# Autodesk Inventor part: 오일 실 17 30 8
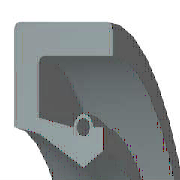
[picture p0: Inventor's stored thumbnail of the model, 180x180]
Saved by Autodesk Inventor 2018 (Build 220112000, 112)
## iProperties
Created: 2012-02
Part Number: 오일 실 17 30 8
Material: 고무
Description: 오일-실
Document SubType Name: Modeling
Standard: KS B 2804
Designer: mduedu
Standards Organization: KS
Language: ko-KR
Size Designation: S - 17 30 8
Categories: <MemberInstance><Categories><Category DisplayName="샤프트 부품" InternalName="7f7aeb1f-a693-4053-b835-cee3144e0d98" Mnemonic="SHFT"><Category DisplayName="실링" Intern
Density: 0.93 g/cm^3
Appearance: 고무 - 검은색 - 버전 1.1
IsCustomPart: 1
Author: mduedu
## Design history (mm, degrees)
revolve "본체" stored, may be unused: angle "d17" = 90 deg
revolve "스프링1" stored, may be unused: angle "d18" = 90 deg
body "Solid1"
sketch "스케치1"
  geometry: L1 (0, 15)-(8, 15); L2 (8, 15)-(8, 13.75); L3 (8, 13.75)-(1.75, 13.75); L4 (0, 15)-(0, 10.6); L5 (0, 10.6)-(1.75, 10.25); L6 (1.75, 10.25)-(4.9, 8.5); L7 (4.9, 8.5)-(0, 8.5); L8 (6.3, 9.375)-(6.3, 10.6); L9 (0, 0)-(9.586, 0) reference; L10 (4.9, 8.5)-(6.3, 9.375); L11 (0, 18)-(0, -3) reference; L12 (-1.917, 0)-(11.503, 0) reference; L13 (4.2, 10.6)-(1.75, 11.09); L14 (1.75, 11.09)-(1.75, 13.75); L15 (6.3, 10.6)-(5.6, 10.6); C1 r 0.455 at (4.9, 10.6); A1 r 0.7 centre (4.9, 10.6) between (5.6, 10.6) and (4.2, 10.6)
  constraints: 26 end point, 5 horizontal alignment, 4 perpendicular, 2 centre point, 2 collinear, 2 horizontal, 2 parallel, 2 point on circle, 2 point on line, 2 vertical alignment, 1 coincident
  dimensions: "d0" = 30 diameter of L1 L9 (= SD2); "d1" = 18.75 diameter of L8.start L9 (= ABDM); "d2" = 1.25 distance of L1.end L2.end (computed from SD); "d3" = 0.91 diameter of C1 (= SPDI); "d4" = 1.4 diameter of A1 (= SPDA); "d5" = 17 diameter of L6.end L9 (= NND); "d6" = 20.5 diameter of L5.end L9 (= TKDM); "d7" = 21.2 diameter of L4.end L9 (= HLDM); "d8" = 4.9 distance from line of C1.centre L4 (= SPDST); "d9" = 6.3 distance between parallel lines of L8 L4 (= SDI); "d10" = 8 distance between parallel lines of L2 L4 (= SWDT); "d12" = 1.75 distance between parallel lines of L14 L4 (= SD)
fillet "모깎기1" dims "d11" = 0.3 (= RR)
other parameters: "SD2" = 30 [user parameter; used in 1 equation term], "SWDT" = 8 [user parameter; used in 1 equation term], "RR" = 0.3 [user parameter; used in 1 equation term], "SD" = 1.75 [user parameter; used in 2 equation terms], "NND" = 17 [user parameter; used in 1 equation term], "SPDA" = 1.4 [user parameter; used in 1 equation term], "SPDI" = 0.91 [user parameter; used in 1 equation term], "TKDM" = 20.5 [user parameter; used in 1 equation term], "HLDM" = 21.2 [user parameter; used in 1 equation term], "ABDM" = 18.75 [user parameter; used in 1 equation term], "SDI" = 6.3 [user parameter; used in 1 equation term], "SPDST" = 4.9 [user parameter; used in 1 equation term], "d13" = 0, "d14" = 0, "d15" = 0, "LAB" = 0.35 [user parameter]
